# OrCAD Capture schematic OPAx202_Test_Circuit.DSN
size A; title: OPAx202 Precision, Low-Noise, Heavy Capacitive Drive, 36-V; rev: 1.4; note: Datasheet: SBOS812H  EVM: N/A
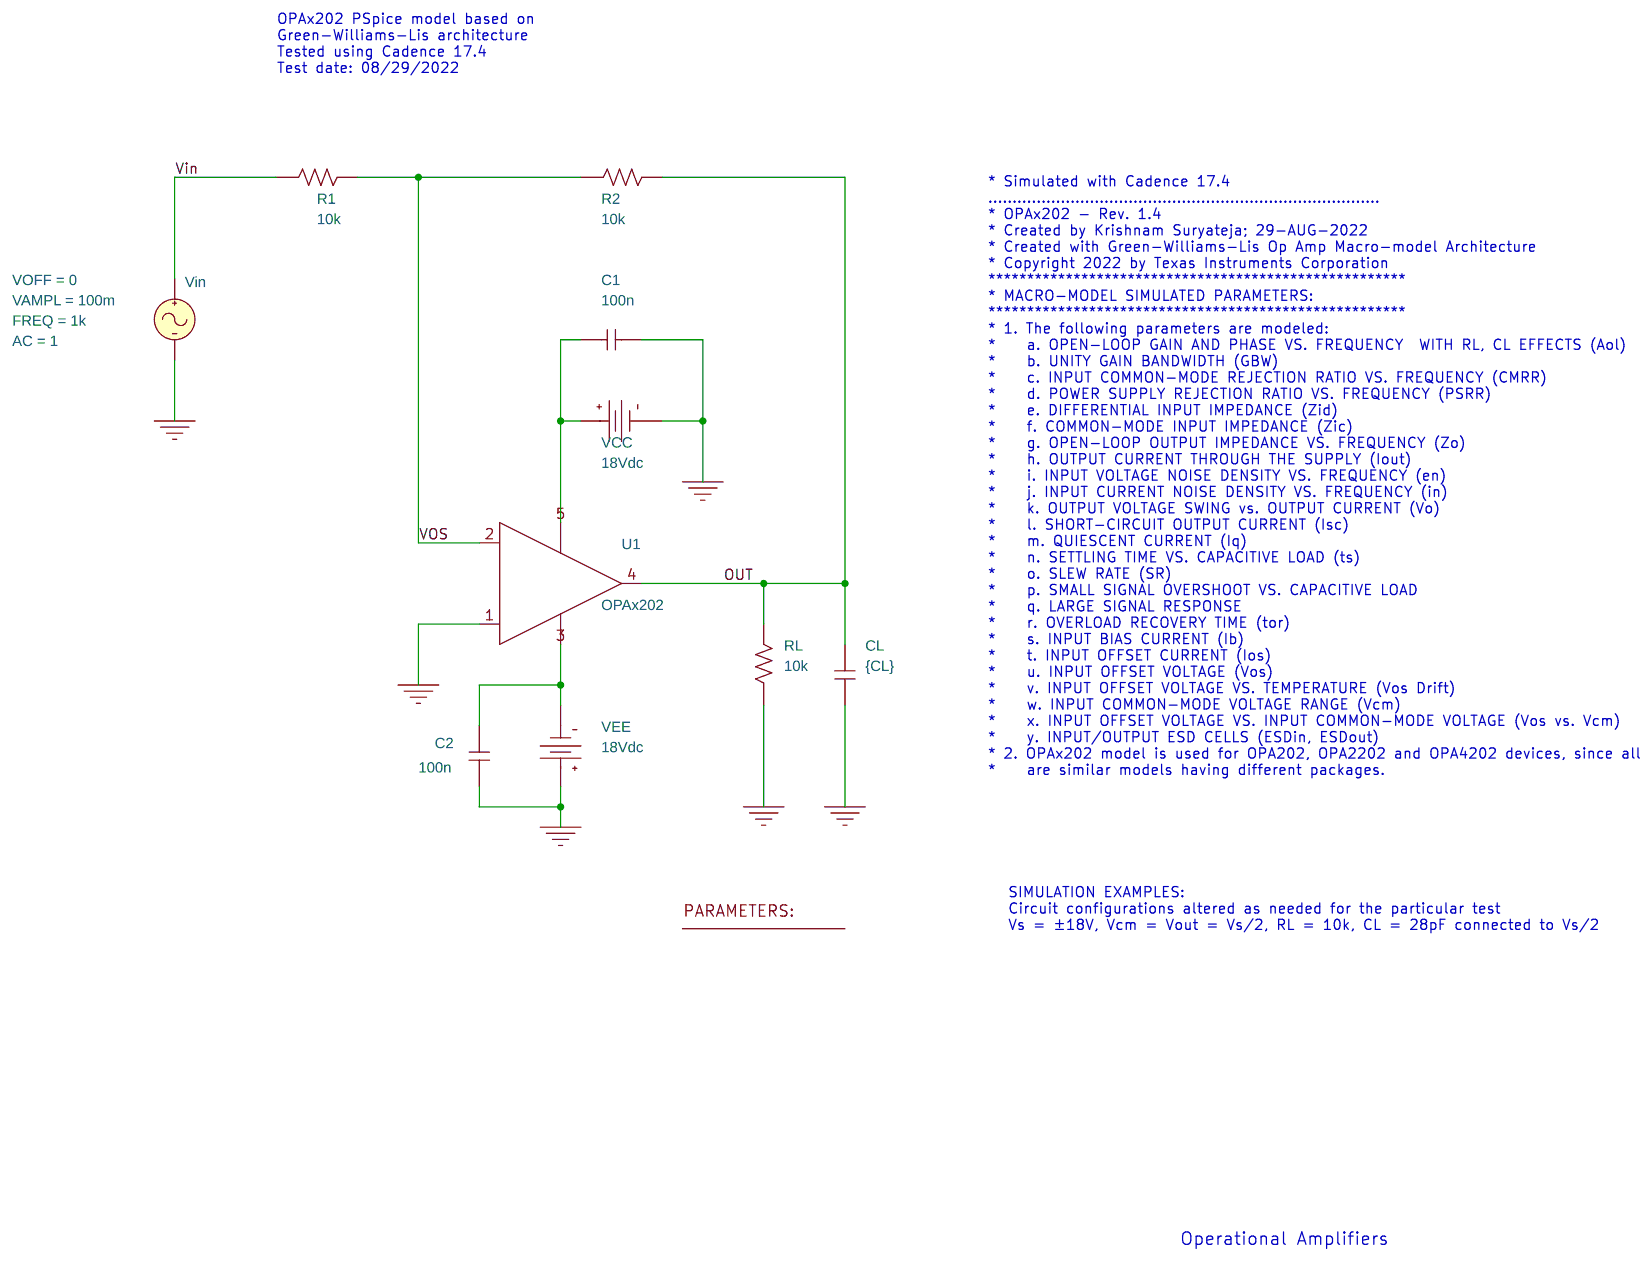
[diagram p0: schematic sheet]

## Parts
1  PARAM
C1  100n  [cap196]
C2  100n  [cap196]
CL  {CL}  [RAD/CK05]
R1  10k  [AXRC05]
R2  10k  [AXRC05]
RL  10k  [AX/RC05]
U1  OPAx202
VCC  VDC
VEE  VDC
Vin  VSIN

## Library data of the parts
1 = PARAM: CL: 28p
C1 C2 CL = C
R1 R2 RL = R
U1 = OPAx202
VCC VEE = VDC: DC: 18Vdc
Vin = VSIN: AC: 1; FREQ: 1k; VAMPL: 100m; VOFF: 0

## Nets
Vin: R1.1 Vin.1(+)
0: C1.2 C2.1 CL.1 RL.1 U1.1(+) VCC.1(-) VEE.0(+) Vin.2(-)
OUT: CL.2 R2.2 RL.2 U1.4(OUT)
VOS: R1.2 R2.1 U1.2(-)
N27303: C1.1 U1.5(V+) VCC.0(+)
N27354: C2.2 U1.3(V-) VEE.1(-)

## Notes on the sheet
- OPAx202 PSpice model based on
  Green-Williams-Lis architecture
  Tested using Cadence 17.4
  Test date: 08/29/2022
- * Simulated with Cadence 17.4
  .................................................................................
  * OPAx202 - Rev. 1.4
  * Created by Krishnam Suryateja; 29-AUG-2022
  * Created with Green-Williams-Lis Op Amp Macro-model Architecture
  * Copyright 2022 by Texas Instruments Corporation
  ******************************************************
  * MACRO-MODEL SIMULATED PARAMETERS:
  ******************************************************
  * 1. The following parameters are modeled:
  *    a. OPEN-LOOP GAIN AND PHASE VS. FREQUENCY  WITH RL, CL EFFECTS (Aol)
  *    b. UNITY GAIN BANDWIDTH (GBW)
  *    c. INPUT COMMON-MODE REJECTION RATIO VS. FREQUENCY (CMRR)
  *    d. POWER SUPPLY REJECTION RATIO VS. FREQUENCY (PSRR)
  *    e. DIFFERENTIAL INPUT IMPEDANCE (Zid)
  *    f. COMMON-MODE INPUT IMPEDANCE (Zic)
  *    g. OPEN-LOOP OUTPUT IMPEDANCE VS. FREQUENCY (Zo)
  *    h. OUTPUT CURRENT THROUGH THE SUPPLY (Iout)
  *    i. INPUT VOLTAGE NOISE DENSITY VS. FREQUENCY (en)
  *    j. INPUT CURRENT NOISE DENSITY VS. FREQUENCY (in)
  *    k. OUTPUT VOLTAGE SWING vs. OUTPUT CURRENT (Vo)
  *    l. SHORT-CIRCUIT OUTPUT CURRENT (Isc)
  *    m. QUIESCENT CURRENT (Iq)
  *    n. SETTLING TIME VS. CAPACITIVE LOAD (ts)
  *    o. SLEW RATE (SR)
  *    p. SMALL SIGNAL OVERSHOOT VS. CAPACITIVE LOAD
  *    q. LARGE SIGNAL RESPONSE
  *    r. OVERLOAD RECOVERY TIME (tor)
  *    s. INPUT BIAS CURRENT (Ib)
  *    t. INPUT OFFSET CURRENT (Ios)
  *    u. INPUT OFFSET VOLTAGE (Vos)
  *    v. INPUT OFFSET VOLTAGE VS. TEMPERATURE (Vos Drift)
  *    w. INPUT COMMON-MODE VOLTAGE RANGE (Vcm)
  *    x. INPUT OFFSET VOLTAGE VS. INPUT COMMON-MODE VOLTAGE (Vos vs. Vcm)
  *    y. INPUT/OUTPUT ESD CELLS (ESDin, ESDout)
  * 2. OPAx202 model is used for OPA202, OPA2202 and OPA4202 devices, since all
  *    are similar models having different packages.
- SIMULATION EXAMPLES:
  Circuit configurations altered as needed for the particular test
  Vs = ±18V, Vcm = Vout = Vs/2, RL = 10k, CL = 28pF connected to Vs/2
- Operational Amplifiers
